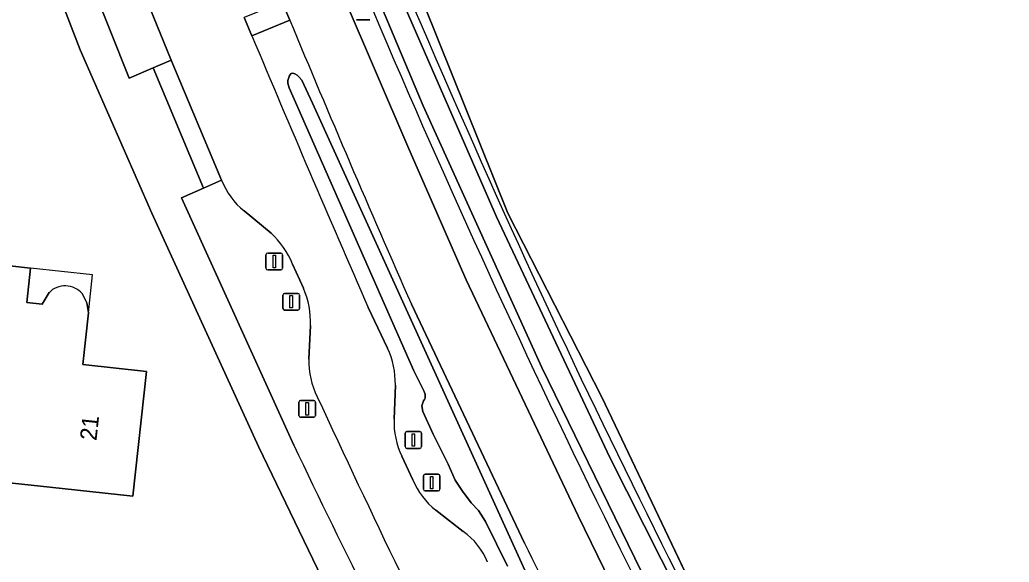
# Model space of a CAD drawing. Extents: x 162396 to 163643, y 386452 to 387406.
# Drawn here: x 163039 to 163098.2, y 386979.1 to 387011.6 of the extents above; entities that cross this region are included whole.
import ezdxf

# ---------------------------------------------------------------- set-up
doc = ezdxf.new("R2010")
doc.units = 0
for name, color, linetype in [('IMGEO_Afsluitpaal', 7, 'Continuous'), ('IMGEO_Berm_groen', 7, 'Continuous'), ('IMGEO_Erf', 7, 'Continuous'), ('IMGEO_Fietspad_gesloten', 7, 'Continuous'), ('IMGEO_Fietspad_halfverhard', 7, 'Continuous'), ('IMGEO_Grasland_agrarisch', 7, 'Continuous'), ('IMGEO_Greppel_droge_sloot', 7, 'Continuous'), ('IMGEO_Hek', 7, 'Continuous'), ('IMGEO_Lichtmast', 7, 'Continuous'), ('IMGEO_Oever', 7, 'Continuous'), ('IMGEO_Pand', 7, 'Continuous'), ('IMGEO_Pand_nummerreeks', 7, 'Continuous'), ('IMGEO_Pand_overbouw', 7, 'Continuous'), ('IMGEO_Parkeervlak_halfverhard', 7, 'Continuous'), ('IMGEO_Rijbaan_lokaal_gesloten', 7, 'Continuous'), ('IMGEO_Rijbaan_lokaal_open', 7, 'Continuous'), ('IMGEO_Voetpad_open', 7, 'Continuous')]:
    doc.layers.add(name, color=color, linetype=linetype)

msp = doc.modelspace()

# ---------------------------------------------------------------- linework, layer by layer
at = {"layer": 'IMGEO_Afsluitpaal'}
for p, q in [((163053.701, 386996.711), (163053.701, 386997.511)), ((163053.701, 386997.511), (163053.701, 386996.711)), ((163053.801, 386997.611), (163054.591, 386997.611)), ((163054.591, 386997.611), (163053.801, 386997.611)), ((163054.691, 386997.511), (163054.691, 386996.711)), ((163054.691, 386996.711), (163054.691, 386997.511)), ((163054.591, 386996.611), (163053.801, 386996.611)), ((163053.801, 386996.611), (163054.591, 386996.611)), ((163054.717, 386994.304), (163054.717, 386995.104)), ((163054.717, 386995.104), (163054.717, 386994.304)), ((163054.817, 386995.204), (163055.607, 386995.204)), ((163055.607, 386995.204), (163054.817, 386995.204)), ((163055.707, 386995.104), (163055.707, 386994.304)), ((163055.707, 386994.304), (163055.707, 386995.104)), ((163055.607, 386994.204), (163054.817, 386994.204)), ((163054.817, 386994.204), (163055.607, 386994.204)), ((163062.03, 386986.027), (163062.03, 386986.827)), ((163062.03, 386986.827), (163062.03, 386986.027)), ((163062.13, 386986.927), (163062.92, 386986.927)), ((163062.92, 386986.927), (163062.13, 386986.927)), ((163063.02, 386986.827), (163063.02, 386986.027)), ((163063.02, 386986.027), (163063.02, 386986.827)), ((163062.92, 386985.927), (163062.13, 386985.927)), ((163062.13, 386985.927), (163062.92, 386985.927)), ((163063.125, 386983.475), (163063.125, 386984.275)), ((163063.125, 386984.275), (163063.125, 386983.475)), ((163063.225, 386984.375), (163064.015, 386984.375)), ((163064.015, 386984.375), (163063.225, 386984.375)), ((163064.115, 386984.275), (163064.115, 386983.475)), ((163064.115, 386983.475), (163064.115, 386984.275)), ((163064.015, 386983.375), (163063.225, 386983.375)), ((163063.225, 386983.375), (163064.015, 386983.375))]:
    msp.add_line(p, q, dxfattribs=at)
for points in [[(163054.121, 386997.486), (163054.271, 386997.486), (163054.271, 386996.736), (163054.121, 386996.736), (163054.121, 386997.486)], [(163055.137, 386995.079), (163055.287, 386995.079), (163055.287, 386994.329), (163055.137, 386994.329), (163055.137, 386995.079)], [(163062.45, 386986.802), (163062.6, 386986.802), (163062.6, 386986.052), (163062.45, 386986.052), (163062.45, 386986.802)], [(163063.545, 386984.25), (163063.695, 386984.25), (163063.695, 386983.5), (163063.545, 386983.5), (163063.545, 386984.25)]]:
    msp.add_lwpolyline(points, dxfattribs=at)
for centre, start, end in [((163053.801, 386997.511), 90, 180), ((163053.801, 386997.511), 90, 180), ((163054.591, 386997.511), 0, 90), ((163054.591, 386997.511), 360, 90), ((163053.801, 386996.711), 180, 270), ((163053.801, 386996.711), 180, 270), ((163054.591, 386996.711), 270, 0), ((163054.591, 386996.711), 270, 0), ((163054.817, 386995.104), 90, 180), ((163054.817, 386995.104), 90, 180), ((163055.607, 386995.104), 0, 90), ((163055.607, 386995.104), 360, 90), ((163054.817, 386994.304), 180, 270), ((163054.817, 386994.304), 180, 270), ((163055.607, 386994.304), 270, 0), ((163055.607, 386994.304), 270, 0), ((163062.13, 386986.827), 90, 180), ((163062.13, 386986.827), 90, 180), ((163062.92, 386986.827), 0, 90), ((163062.92, 386986.827), 360, 90), ((163062.13, 386986.027), 180, 270), ((163062.13, 386986.027), 180, 270), ((163062.92, 386986.027), 270, 0), ((163062.92, 386986.027), 270, 0), ((163063.225, 386984.275), 90, 180), ((163063.225, 386984.275), 90, 180), ((163064.015, 386984.275), 0, 90), ((163064.015, 386984.275), 360, 90), ((163063.225, 386983.475), 180, 270), ((163063.225, 386983.475), 180, 270), ((163064.015, 386983.475), 270, 0), ((163064.015, 386983.475), 270, 0)]:
    msp.add_arc(centre, 0.1, start, end, dxfattribs=at)
at = {"layer": 'IMGEO_Berm_groen'}
for points in [[(163081.917, 386971.38), (163082.23, 386970.809), (163082.411, 386970.924), (163073.808, 386988.989), (163068.186, 387000), (163054.818, 387033.276), (163053.682, 387034.148), (163050.906, 387033.096), (163050.522, 387032.951), (163051.574, 387030.199)], [(163058.321, 387013.033), (163062.245, 387003.85), (163065.679, 386996.007), (163072.387, 386981.888), (163076.252, 386973.982), (163079.946, 386966.717), (163082.017, 386962.946), (163085.197, 386957.174), (163087.753, 386952.543), (163088.198, 386951.737), (163088.644, 386950.931), (163089.035, 386950.226), (163090.045, 386948.352), (163091.713, 386945.359), (163103.715, 386924.646), (163109.912, 386913.996), (163113.552, 386907.796), (163119.49, 386897.68), (163133.047, 386874.854), (163141.068, 386861.652), (163143.895, 386857.051), (163155.065, 386838.871)], [(163055.12, 387011.562), (163052.862, 387010.617)], [(163068.158, 386978.883), (163066.846, 386981.552), (163066.421, 386982.203), (163065.99, 386982.657), (163065.461, 386983.357), (163065.029, 386984.021), (163064.619, 386984.989), (163063.71, 386986.769), (163063.085, 386988.135), (163063.025, 386988.474), (163063.138, 386988.769), (163063.191, 386988.844), (163063.23, 386988.926), (163063.23, 386989.03), (163063.23, 386989.149), (163063.168, 386989.324), (163062.557, 386990.57), (163055.082, 387007.505), (163055.016, 387007.789), (163055.017, 387007.948), (163055.104, 387008.252), (163055.206, 387008.362), (163055.302, 387008.382), (163055.431, 387008.346), (163055.566, 387008.262), (163055.697, 387008.145), (163055.844, 387007.972), (163056.486, 387006.585), (163074.609, 386966.738)], [(163051.044, 387001.979), (163049.965, 387001.496), (163048.634, 387000.913), (163055.369, 386986.116)], [(163054.002, 386998.81), (163052.388, 387000.142)], [(163055.939, 386995.505), (163055.297, 386996.958)], [(163059.829, 386994.357), (163060.977, 386991.932)], [(163069.176, 386980.249), (163062.41, 386994.55)], [(163056.262, 386991.269), (163056.36, 386993.273)], [(163061.448, 386989.718), (163061.37, 386987.665)], [(163061.838, 386985.454), (163062.49, 386984.051)], [(163063.865, 386982.216), (163065.512, 386980.95)]]:
    msp.add_lwpolyline(points, dxfattribs=at)
for centre, radius, start, end in [((163799.605, 387329.13), 802.258, 201.654195, 204.22085), ((163617.483, 387248.752), 605.525, 201.981516, 208.497735), ((163923.474, 387373.602), 940.804, 202.632561, 203.759743), ((164021.44, 387416.005), 1049.992, 202.711261, 203.676563), ((163055.153, 387003.575), 4.408, 201.22878, 231.15169), ((163589.339, 387236.382), 572.453, 204.38886, 207.57586), ((163050.225, 386994.79), 5.516, 23.1428, 46.78309), ((163051.475, 386993.507), 4.89, 357.25297, 24.11031), ((163056.433, 386989.808), 5.016, 358.96996, 25.04984), ((163060.996, 386991.153), 4.736, 178.59135, 206.92735), ((163688.17, 387280.781), 695.552, 204.802003, 206.714116), ((163066.053, 386987.501), 4.686, 177.99748, 205.90519), ((163393.942, 387145.824), 374.35, 205.25364, 208.51204), ((163066.846, 386985.882), 4.725, 202.80352, 230.8863), ((163063.135, 386977.576), 4.127, 21.82962, 54.83349), ((163849.84, 387363.51), 869.67, 206.148358, 207.194709)]:
    msp.add_arc(centre, radius, start, end, dxfattribs=at)
at = {"layer": 'IMGEO_Erf'}
for points in [[(163074.122, 386945.175), (163067.344, 386957.823), (163057.319, 386977.598), (163053.248, 386986.028), (163046.866, 387000), (163042.57, 387009.785), (163041.387, 387012.856), (163030.729, 387041.536), (163024.497, 387061.137), (163016.462, 387091.359)], [(163024.353, 386989.835), (163024.972, 386995.528), (163026.251, 386995.39), (163026.574, 386998.747), (163026.694, 387000), (163027.051, 387003.724), (163031.413, 387003.25), (163036.652, 387002.68), (163036.361, 387000), (163036.046, 386997.103), (163039.606, 386996.715), (163039.383, 386994.664), (163040.293, 386994.565), (163040.71, 386995.245)], [(163042.696, 386995.186), (163042.979, 386994.643), (163043.07, 386994.037), (163042.734, 386990.948), (163046.537, 386990.534), (163045.724, 386983.055), (163040.754, 386983.595), (163035.888, 386984.124), (163036.022, 386985.361), (163030.75, 386985.934), (163031.034, 386988.55), (163031.713, 386994.796), (163027.664, 386995.236), (163027.045, 386989.543), (163024.353, 386989.835)]]:
    msp.add_lwpolyline(points, dxfattribs=at)
msp.add_arc((163041.676, 386994.313), 1.342, 40.55033, 136.04639, dxfattribs=at)
at = {"layer": 'IMGEO_Fietspad_gesloten'}
for points in [[(163054.675, 387012.637), (163055.12, 387011.562)], [(163155.065, 386838.871), (163143.895, 386857.051), (163141.068, 386861.652), (163133.047, 386874.854), (163119.49, 386897.68), (163113.552, 386907.796), (163109.912, 386913.996), (163103.715, 386924.646), (163091.713, 386945.359), (163090.045, 386948.352), (163089.035, 386950.226), (163088.644, 386950.931), (163088.198, 386951.737), (163087.753, 386952.543), (163085.197, 386957.174), (163082.017, 386962.946), (163079.946, 386966.717), (163076.252, 386973.982), (163072.387, 386981.888), (163065.679, 386996.007), (163062.245, 387003.85), (163058.321, 387013.033)], [(163062.41, 386994.55), (163069.176, 386980.249)]]:
    msp.add_lwpolyline(points, dxfattribs=at)
for centre, radius, start, end in [((163923.474, 387373.602), 940.804, 202.632561, 203.759743), ((163849.84, 387363.51), 869.67, 206.148358, 207.194709)]:
    msp.add_arc(centre, radius, start, end, dxfattribs=at)
at = {"layer": 'IMGEO_Fietspad_halfverhard'}
msp.add_lwpolyline([(163054.675, 387012.637), (163052.398, 387011.715), (163052.862, 387010.617), (163055.12, 387011.562)], close=True, dxfattribs=at)
at = {"layer": 'IMGEO_Grasland_agrarisch'}
msp.add_lwpolyline([(163133.622, 387049.496), (163133.622, 387043.535), (163132.797, 387029.52), (163128.519, 387010.953), (163118.136, 387014.933), (163098.941, 387022.102), (163077.233, 387030.06), (163058.746, 387037.469), (163054.818, 387033.276), (163068.186, 387000), (163073.808, 386988.989), (163082.411, 386970.924), (163083.129, 386969.417), (163091.34, 386954.37), (163094.029, 386949.441), (163096.403, 386944.93), (163098.137, 386941.992), (163116.399, 386910.212)], dxfattribs=at)
at = {"layer": 'IMGEO_Greppel_droge_sloot'}
for points in [[(163056.44, 387022.287), (163063.106, 387006.428), (163070.219, 386990.766), (163077.774, 386975.312)], [(163081.474, 386971.147), (163074.294, 386985.374), (163067.514, 386999.794), (163060.321, 387016.274)], [(163074.609, 386966.738), (163056.486, 387006.585), (163055.844, 387007.972), (163055.697, 387008.145), (163055.566, 387008.262), (163055.431, 387008.346), (163055.302, 387008.382), (163055.206, 387008.362), (163055.104, 387008.252), (163055.017, 387007.948), (163055.016, 387007.789), (163055.082, 387007.505), (163062.557, 386990.57), (163063.168, 386989.324), (163063.23, 386989.149), (163063.23, 386989.03), (163063.23, 386988.926), (163063.191, 386988.844), (163063.138, 386988.769), (163063.025, 386988.474), (163063.085, 386988.135), (163063.71, 386986.769), (163064.619, 386984.989), (163065.029, 386984.021), (163065.461, 386983.357), (163065.99, 386982.657), (163066.421, 386982.203), (163066.846, 386981.552), (163068.158, 386978.883)]]:
    msp.add_lwpolyline(points, dxfattribs=at)
at = {"layer": 'IMGEO_Hek'}
msp.add_lwpolyline([(163119.211, 386906.146), (163099.887, 386939.051), (163083.129, 386969.417), (163073.808, 386988.989), (163068.186, 387000), (163054.818, 387033.276)], dxfattribs=at)
at = {"layer": 'IMGEO_Lichtmast'}
for p, q in [((163059.92, 387011.578), (163059.13, 387011.578)), ((163059.13, 387011.578), (163059.92, 387011.578)), ((163055.769, 386988.793), (163056.559, 386988.793)), ((163056.559, 386988.793), (163055.769, 386988.793)), ((163055.669, 386987.893), (163055.669, 386988.693)), ((163055.669, 386988.693), (163055.669, 386987.893)), ((163056.659, 386988.693), (163056.659, 386987.893)), ((163056.659, 386987.893), (163056.659, 386988.693)), ((163056.559, 386987.793), (163055.769, 386987.793)), ((163055.769, 386987.793), (163056.559, 386987.793))]:
    msp.add_line(p, q, dxfattribs=at)
msp.add_lwpolyline([(163056.089, 386988.668), (163056.239, 386988.668), (163056.239, 386987.918), (163056.089, 386987.918), (163056.089, 386988.668)], dxfattribs=at)
for centre, start, end in [((163055.769, 386988.693), 90, 180), ((163055.769, 386988.693), 90, 180), ((163056.559, 386988.693), 0, 90), ((163056.559, 386988.693), 360, 90), ((163055.769, 386987.893), 180, 270), ((163055.769, 386987.893), 180, 270), ((163056.559, 386987.893), 270, 0), ((163056.559, 386987.893), 270, 0)]:
    msp.add_arc(centre, 0.1, start, end, dxfattribs=at)
at = {"layer": 'IMGEO_Oever'}
for points in [[(163077.774, 386975.312), (163070.219, 386990.766), (163063.106, 387006.428), (163056.44, 387022.287)], [(163060.321, 387016.274), (163067.514, 386999.794), (163074.294, 386985.374), (163081.474, 386971.147)]]:
    msp.add_lwpolyline(points, dxfattribs=at)
for centre, radius, start, end in [((163799.605, 387329.13), 802.258, 201.654195, 204.22085), ((163617.483, 387248.752), 605.525, 201.981516, 208.497735), ((163589.339, 387236.382), 572.453, 204.38886, 207.57586)]:
    msp.add_arc(centre, radius, start, end, dxfattribs=at)
at = {"layer": 'IMGEO_Pand'}
for points in [[(163040.71, 386995.245), (163040.293, 386994.565), (163039.383, 386994.664), (163039.606, 386996.715), (163036.046, 386997.103)], [(163043.07, 386994.037), (163042.979, 386994.643), (163042.696, 386995.186)], [(163035.888, 386984.124), (163040.754, 386983.595), (163045.724, 386983.055), (163046.537, 386990.534), (163042.734, 386990.948), (163043.07, 386994.037)]]:
    msp.add_lwpolyline(points, dxfattribs=at)
msp.add_arc((163041.676, 386994.313), 1.342, 40.55033, 136.04639, dxfattribs=at)
at = {"layer": 'IMGEO_Pand_overbouw'}
msp.add_lwpolyline([(163042.696, 386995.186), (163042.979, 386994.643), (163043.07, 386994.037), (163043.317, 386996.31), (163039.606, 386996.715), (163039.383, 386994.664), (163040.293, 386994.565), (163040.71, 386995.245)], dxfattribs=at)
msp.add_arc((163041.676, 386994.313), 1.342, 40.55033, 136.04639, dxfattribs=at)
at = {"layer": 'IMGEO_Parkeervlak_halfverhard'}
msp.add_lwpolyline([(163045.696, 387014.905), (163043.199, 387013.906), (163045.502, 387008.094), (163046.946, 387008.701), (163048.025, 387009.155)], close=True, dxfattribs=at)
at = {"layer": 'IMGEO_Rijbaan_lokaal_gesloten'}
for points in [[(163020.527, 387092.428), (163022.191, 387085.621), (163023.779, 387079.82), (163025.427, 387073.976), (163032.848, 387049.845), (163034.765, 387044.176), (163036.769, 387038.48), (163045.696, 387014.905), (163048.025, 387009.155), (163051.044, 387001.979)], [(163052.862, 387010.617), (163052.398, 387011.715)], [(163052.388, 387000.142), (163054.002, 386998.81)], [(163055.297, 386996.958), (163055.939, 386995.505)], [(163060.977, 386991.932), (163059.829, 386994.357)], [(163056.36, 386993.273), (163056.262, 386991.269)], [(163061.37, 386987.665), (163061.448, 386989.718)], [(163062.49, 386984.051), (163061.838, 386985.454)], [(163065.512, 386980.95), (163063.865, 386982.216)]]:
    msp.add_lwpolyline(points, dxfattribs=at)
for centre, radius, start, end in [((164021.44, 387416.005), 1049.992, 202.711261, 203.676563), ((163055.153, 387003.575), 4.408, 201.22878, 231.15169), ((163050.225, 386994.79), 5.516, 23.1428, 46.78309), ((163051.475, 386993.507), 4.89, 357.25297, 24.11031), ((163056.433, 386989.808), 5.016, 358.96996, 25.04984), ((163060.996, 386991.153), 4.736, 178.59135, 206.92735), ((163688.17, 387280.781), 695.552, 204.802003, 206.714116), ((163066.053, 386987.501), 4.686, 177.99748, 205.90519), ((163066.846, 386985.882), 4.725, 202.80352, 230.8863), ((163063.135, 386977.576), 4.127, 21.82962, 54.83349)]:
    msp.add_arc(centre, radius, start, end, dxfattribs=at)
at = {"layer": 'IMGEO_Rijbaan_lokaal_open'}
msp.add_lwpolyline([(163048.025, 387009.155), (163046.946, 387008.701), (163049.965, 387001.496), (163051.044, 387001.979)], close=True, dxfattribs=at)
at = {"layer": 'IMGEO_Voetpad_open'}
for points in [[(163016.462, 387091.359), (163024.497, 387061.137), (163030.729, 387041.536), (163041.387, 387012.856), (163042.57, 387009.785), (163046.866, 387000), (163053.248, 386986.028), (163057.319, 386977.598), (163067.344, 386957.823), (163074.122, 386945.175), (163079.761, 386934.958), (163102.006, 386895.698), (163123.585, 386859.49), (163143.068, 386827.803)], [(163055.369, 386986.116), (163048.634, 387000.913), (163049.965, 387001.496), (163046.946, 387008.701), (163045.502, 387008.094), (163043.199, 387013.906), (163038.187, 387026.999), (163034.229, 387037.607), (163035.657, 387038.086), (163033.677, 387043.806), (163032.283, 387043.335), (163030.398, 387049.014)]]:
    msp.add_lwpolyline(points, dxfattribs=at)
msp.add_arc((163393.942, 387145.824), 374.35, 205.25364, 208.51204, dxfattribs=at)

# ---------------------------------------------------------------- texts
at = {"layer": 'IMGEO_Pand_nummerreeks'}
msp.add_text('21', height=1, rotation=83.79508, dxfattribs=at).set_placement((163043.547, 386986.358))

doc.saveas('drawing.dxf')
